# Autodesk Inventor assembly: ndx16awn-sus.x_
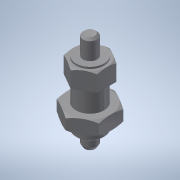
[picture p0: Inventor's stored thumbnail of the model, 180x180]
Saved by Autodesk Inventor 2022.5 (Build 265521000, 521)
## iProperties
Part Number: ndx16awn-sus.x_
Material: 一般
Document SubType Name: Assembly
Designer: ImaoCorp
Sending System: SOLIDWORKS 2017-2017317
MC: AMD64
MC_MODEL: Intel64 Family 6 Model 60 Stepping 3, GenuineIntel
OS: Windows_NT
FRU: Parasolid Version 29.0, build 201,  4-17-2017
FORMAT: text
GUISE: transmit
KEY: ndx16awn-sus
FILE: ndx16awn-sus.x_t
DATE: Wed Sep 04 15:30:59 2019
Author: ImaoCorp
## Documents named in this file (3)
- X:\14_SW2022-Inv2022\00_全2023-1023新製品(TCC)まで\n\ndx16awn-sus\NDX16AWN-SUS.iam
- X:\14_SW2022-Inv2022\00_全2023-1023新製品(TCC)まで\n\ndx16awn-sus\ndx16awn-sus_01.ipt
- X:\14_SW2022-Inv2022\00_全2023-1023新製品(TCC)まで\n\ndx16awn-sus\ndx16awn-sus_02.ipt
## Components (2 placed, 2 different names)
1. ndx16awn-sus_01
2. ndx16awn-sus_02
